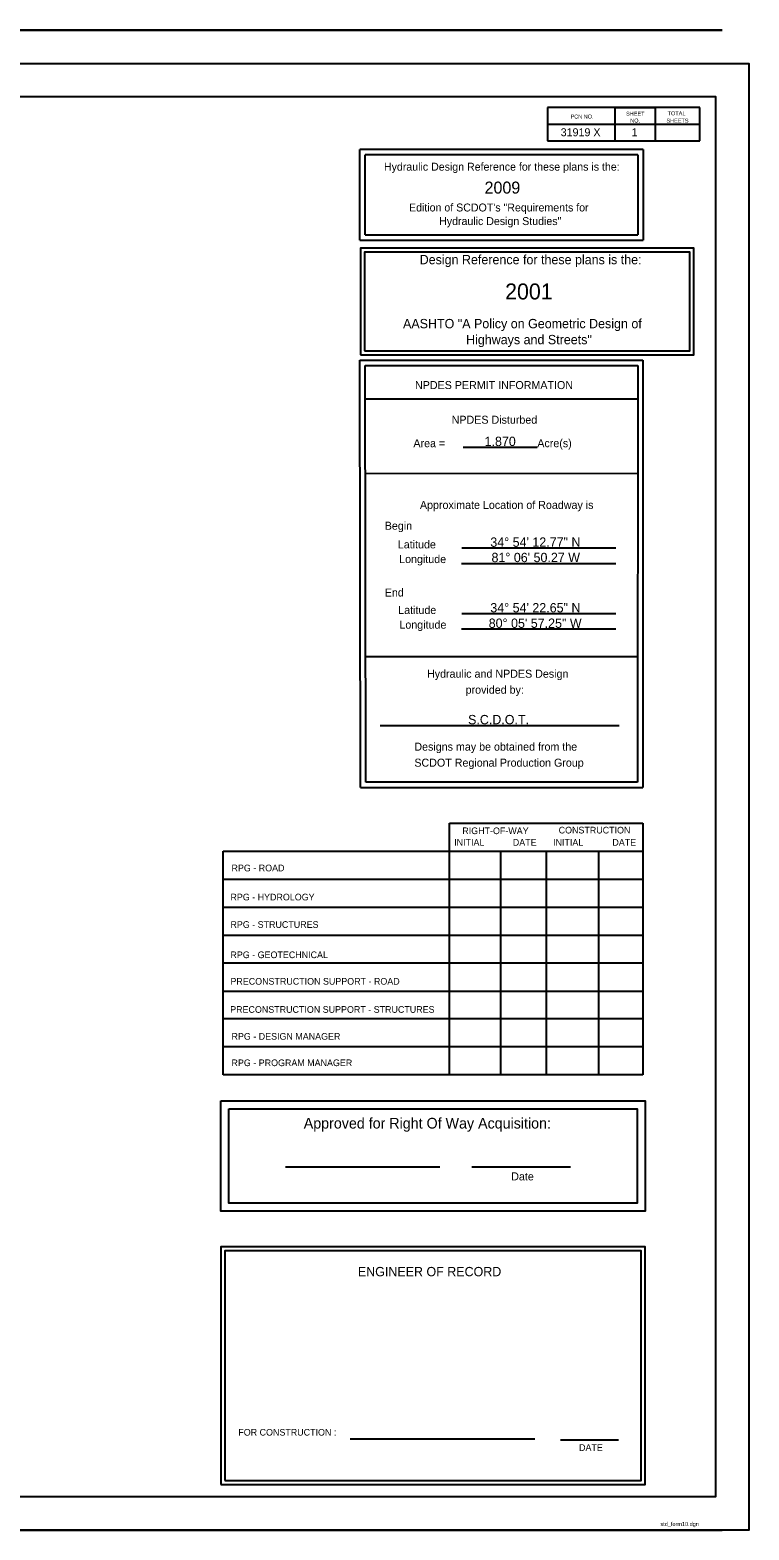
# Model space of a CAD drawing. Extents: x 8134 to 11793, y 3225 to 13425.
# Drawn here: x 11241 to 11780, y 10000 to 11125 of the extents above; entities that cross this region are included whole.
import ezdxf

# ---------------------------------------------------------------- set-up
doc = ezdxf.new("R2010")
doc.units = 0
for name, color, linetype in [('RD_SHT_Bndy', 7, 'Continuous'), ('RD_SHT_IplotShp', 7, 'Continuous'), ('RD_SHT_TX', 7, 'Continuous'), ('RD_TX_TitleSht', 7, 'Continuous')]:
    doc.layers.add(name, color=color, linetype=linetype)

msp = doc.modelspace()

# ---------------------------------------------------------------- linework, layer by layer
at = {"layer": 'RD_SHT_Bndy'}
for p, q in [((10000, 11125), (11760, 11125)), ((11760, 11125), (10000, 11125)), ((10000, 11100), (11760, 11100)), ((11743.3, 11066.8), (11628.8, 11066.8)), ((11628.8, 11066.8), (11628.8, 11041.8)), ((11679.8, 11041.8), (11679.8, 11066.8)), ((11679.8, 11066.8), (11709.8, 11066.8)), ((11709.8, 11066.8), (11709.8, 11041.8)), ((11743.3, 11041.8), (11743.3, 11066.8)), ((11628.8, 11054.3), (11742.9, 11054.3)), ((11628.8, 11041.8), (11743.3, 11041.8)), ((11649.8, 11041.8), (11700.8, 11041.8)), ((11700.6, 11035.4), (11488.1, 11035.4)), ((11488.2, 10967.4), (11488.1, 11035.4)), ((11492.1, 10971.3), (11492, 11031.4)), ((11696.7, 11031.4), (11492, 11031.4)), ((11696.7, 11031.4), (11696.7, 10971.4)), ((11700.6, 11035.4), (11700.6, 10967.4)), ((11492.1, 10971.3), (11696.7, 10971.4)), ((11488.2, 10967.4), (11700.6, 10967.4)), ((11488.1, 10877.3), (11700.5, 10877.3)), ((11488.5, 10556.9), (11488.1, 10877.3)), ((11492.1, 10873.3), (11696.6, 10873.4)), ((11492.6, 10560.8), (11492.1, 10873.3)), ((11696.6, 10873.4), (11696.4, 10560.8)), ((11700.5, 10877.3), (11700.4, 10556.9)), ((11492.2, 10848.5), (11696.6, 10848.5)), ((11565.6, 10812.2), (11621.1, 10812.2)), ((11492.2, 10792.4), (11696.4, 10792.6)), ((11564.7, 10736.6), (11680.3, 10736.6)), ((11564.5, 10725), (11680.1, 10725)), ((11564.7, 10687.4), (11680.3, 10687.4)), ((11564.5, 10675.8), (11680.1, 10675.8)), ((11696.5, 10654.8), (11492.4, 10654.8)), ((11503.3, 10603.4), (11682.7, 10603.4)), ((11696.4, 10560.8), (11492.6, 10560.8)), ((11555.5, 10341.3), (11555.5, 10530.2)), ((11555.5, 10530.2), (11700.4, 10530.2)), ((11700.4, 10530.2), (11700.4, 10341.3)), ((11385.5, 10509.2), (11700.4, 10509.2)), ((11385.5, 10341.3), (11385.5, 10509.2)), ((11593.7, 10509.2), (11593.7, 10341.3)), ((11627.9, 10509.2), (11627.9, 10341.3)), ((11667.3, 10509.2), (11667.3, 10341.3)), ((11385.5, 10488.2), (11700.4, 10488.2)), ((11385.5, 10467.2), (11700.4, 10467.2)), ((11385.5, 10446.2), (11700.4, 10446.2)), ((11700.4, 10446.2), (11700.4, 10425.2)), ((11700.4, 10425.2), (11385.5, 10425.2)), ((11385.5, 10404.2), (11700.4, 10404.2)), ((11700.4, 10404.2), (11700.4, 10383.3)), ((11700.4, 10383.3), (11385.5, 10383.3)), ((11700.4, 10362.3), (11385.5, 10362.3)), ((11700.4, 10341.3), (11385.5, 10341.3)), ((11432.4, 10272.5), (11548, 10272.5)), ((11572.1, 10272.5), (11646.2, 10272.5)), ((11480.9, 10068.3), (11619.5, 10068.3)), ((11638.6, 10067.7), (11682.1, 10067.7)), ((10000, 10000), (11760, 10000)), ((11760, 10000), (10000, 10000))]:
    msp.add_line(p, q, dxfattribs=at)
for points in [[(10079.6, 11075.1), (11755.1, 11075.1), (11755.1, 10025), (10079.6, 10025)], [(11383.9, 10321.8), (11702.1, 10321.8), (11702.1, 10239.1), (11383.9, 10239.1)], [(11389.9, 10315.8), (11696.1, 10315.8), (11696.1, 10245.1), (11389.9, 10245.1)], [(11383.9, 10034.1), (11702.1, 10034.1), (11702.1, 10212.4), (11383.9, 10212.4)], [(11386.9, 10037.1), (11699.1, 10037.1), (11699.1, 10209.4), (11386.9, 10209.4)]]:
    msp.add_lwpolyline(points, close=True, dxfattribs=at)
msp.add_lwpolyline([(11488.5, 10556.9), (11700.4, 10556.9)], dxfattribs=at)
at = {"layer": 'RD_SHT_IplotShp'}
msp.add_lwpolyline([(9984.1, 11100), (11780.1, 11100), (11780.1, 10000), (9984.1, 10000)], close=True, dxfattribs=at)
at = {"layer": 'RD_TX_TitleSht'}
for points in [[(11488.7, 10881.4), (11738.7, 10881.4), (11738.7, 10961.4), (11488.7, 10961.4)], [(11491.7, 10884.4), (11735.7, 10884.4), (11735.7, 10958.4), (11491.7, 10958.4)]]:
    msp.add_lwpolyline(points, close=True, dxfattribs=at)

# ---------------------------------------------------------------- texts
at = {"layer": 'RD_SHT_TX'}
for s, height, p in [('PCN NO.', 3, (11646.2, 11058.6)), ('SHEET', 3, (11687.9, 11060.7)), ('TOTAL', 3, (11719.1, 11061)), ('NO.', 3, (11691, 11055.6)), ('SHEETS', 3, (11718.2, 11055.5)), ('NPDES PERMIT INFORMATION', 6, (11529.5, 10855.7)), ('NPDES Disturbed', 6, (11557, 10829.7)), ('Area =                               Acre(s)', 6, (11528.3, 10812.1)), ('Approximate Location of Roadway is', 6, (11533.2, 10765.8)), ('Begin', 6, (11506.8, 10750.2)), ('Latitude', 6, (11516.6, 10736.2)), ('Longitude', 6, (11517.6, 10725.2)), ('End', 6, (11506.8, 10700.1)), ('Latitude', 6, (11516.9, 10687)), ('Longitude', 6, (11517.8, 10676)), ('Hydraulic and NPDES Design', 6, (11538.5, 10639.2)), ('             provided by:', 6, (11538.5, 10627.2)), ('Designs may be obtained from the ', 6, (11529, 10584.5)), ('SCDOT Regional Production Group', 6, (11529, 10572.5)), ('RPG - ROAD', 5, (11391.8, 10494)), ('RPG - HYDROLOGY ', 4.998, (11391, 10472.2)), ('RPG - STRUCTURES', 4.998, (11391, 10451.6)), ('RPG - GEOTECHNICAL', 4.998, (11391, 10428.9)), ('PRECONSTRUCTION SUPPORT - ROAD', 4.998, (11391, 10409)), ('PRECONSTRUCTION SUPPORT - STRUCTURES', 4.998, (11390.8, 10387.9)), ('RPG - DESIGN MANAGER', 4.998, (11391.8, 10367.7)), ('RPG - PROGRAM MANAGER', 4.998, (11391.8, 10347.9)), ('Approved for Right Of Way Acquisition:', 8, (11446, 10301.1)), ('Date', 6, (11601.7, 10262.2)), ('ENGINEER OF RECORD', 7, (11486.6, 10190.3)), ('FOR CONSTRUCTION :', 5, (11396.9, 10070.8)), ('DATE', 5, (11652.6, 10059.3)), ('std_form10.dgn', 3, (11713.7, 10003))]:
    msp.add_text(s, height=height, dxfattribs=at).set_placement(p)
for s, height, p in [('RIGHT-OF-WAY', 4.998, (11565, 10521.9)), ('CONSTRUCTION', 4.998, (11637.3, 10522.4)), ('INITIAL', 5, (11558.9, 10513.2)), ('DATE', 5, (11602.9, 10513.2)), ('INITIAL', 5, (11633.1, 10513.2)), ('DATE', 5, (11677.6, 10513.2))]:
    msp.add_text(s, height=height, rotation=360, dxfattribs=at).set_placement(p)
at = {"layer": 'RD_TX_TitleSht'}
for s, height, p in [('31919 X', 6, (11638.8, 11045.3)), ('1', 6, (11692, 11045.3)), ('Hydraulic Design Reference for these plans is the:', 5.949, (11506.2, 11019.5)), ('2009', 9, (11581.7, 11002.3)), ('Edition of SCDOT\'s "Requirements for ', 5.949, (11525, 10988.9)), ('Hydraulic Design Studies"', 5.949, (11547.6, 10978.7)), ('Design Reference for these plans is the:', 7, (11533, 10949.3)), ('2001', 12, (11597.1, 10922.9)), ('AASHTO "A Policy on Geometric Design of ', 7, (11520.5, 10901.3)), ('Highways and Streets"', 7, (11567.8, 10889.3)), ('1.870', 7, (11581.7, 10813)), ('34%%d 54\' 12.77" N', 7, (11586, 10737.4)), ("81%%d 06' 50.27 W", 7, (11586.9, 10725.9)), ('34%%d 54\' 22.65" N', 7, (11586, 10688.2)), ('80%%d 05\' 57.25" W', 7, (11584.8, 10676.6)), ('S.C.D.O.T.', 7, (11569.3, 10604.3))]:
    msp.add_text(s, height=height, dxfattribs=at).set_placement(p)

doc.saveas('drawing.dxf')
